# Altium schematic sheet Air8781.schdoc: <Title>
size 419 x 266 mm; Name: SIZEB; Symbol: SIZEB; Device: SIZEB; Drawn By: <Drawn By>; Checked By: <Checked By>; QC By: <QC By>; Released By: <Released By>; Drawn Date: <Drawn Date>; Checked Date: <Checked Date>; QC Date: <QC Date>; Release Date: <Release Date>; Company Name: <Company Name>; Code: <Code>; Sheet Size: B; Drawing Number: <Drawing Number>; Revision: <Revision>; Scale: <Scale>; Sheet Number: 1; Number of Sheets: 1
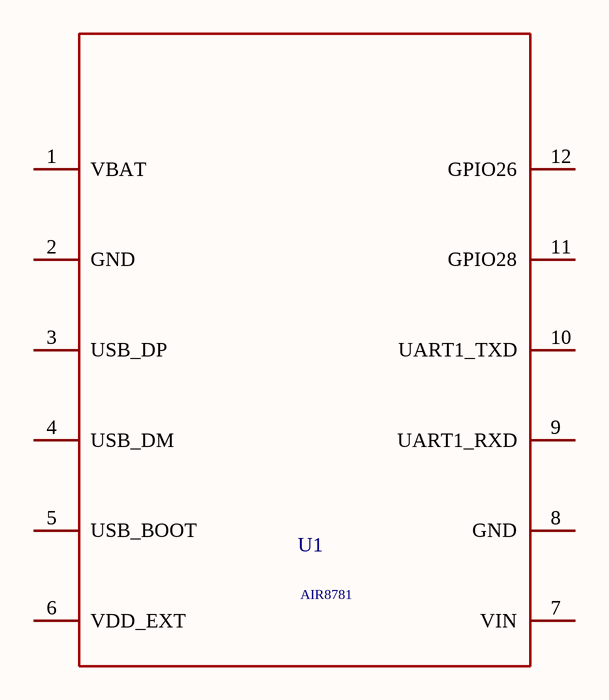
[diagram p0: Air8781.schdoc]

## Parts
U1  AIR8781

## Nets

Not connected (* = marked no-connect by the designer): U1 1(VBAT) 2(GND) 3(USB_DP) 4(USB_DM) 5(USB_BOOT) 6(VDD_EXT) 7(VIN) 8(GND) 9(UART1_RXD) 10(UART1_TXD) 11(GPIO28) 12(GPIO26)

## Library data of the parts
U1 = AIR8781: Add into BOM: yes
